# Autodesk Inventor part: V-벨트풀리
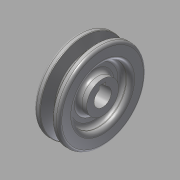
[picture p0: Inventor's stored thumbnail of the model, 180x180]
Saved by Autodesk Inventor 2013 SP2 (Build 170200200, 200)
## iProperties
Created: 2015-12
Part Number: V-벨트풀리
Material: 강철, 연강
Document SubType Name: Modeling
Designer: mduedu
Density: 7.86 g/cm^3
Author: mduedu
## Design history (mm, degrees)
sketch "스케치1"
  geometry: L1 (-9.5, 0)-(9.5, 0); L2 (-9.5, 0)-(-9.5, 32.7); L3 (-9.5, 32.7)-(-4.825, 32.7); L4 (-4.825, 32.7)-(-2.074, 23.7); L5 (-2.074, 23.7)-(0, 23.7); L6 (0, 0)-(0, 23.7); L7 (9.5, 0)-(9.5, 32.7); L8 (9.5, 32.7)-(4.825, 32.7); L9 (4.825, 32.7)-(2.074, 23.7); L10 (2.074, 23.7)-(0, 23.7); L11 (-4, 30)-(4, 30); 3 further points
  constraints: 22 end point, 3 coincident, 3 perpendicular, 3 symmetric about line, 2 parallel, 2 point on line, 1 horizontal, 1 midpoint, 1 vertical alignment
  dimensions: "d0" = 19 distance between parallel lines of L7 L2; "d2" = 6.3 distance between parallel lines of L10 L11; "d3" = 34 deg angle of L9 L4; "d4" = 2.7 distance between parallel lines of L11 L8; "d5" = 60 diameter of L11 L1; "d6" = 8 distance of L11.end L11.start
revolve "회전1" sketch "스케치1" stored, may be unused: angle "d7" = 90 deg
sketch "스케치2"
  geometry: C1 r 21 at (0, 0); C2 r 12 at (0, 0); 1 further point
  constraints: 2 centre point, 2 coincident
  dimensions: "d8" = 42 diameter of C1; "d10" = 24 diameter of C2
extrude "돌출1" cut sketch "스케치2" distance "d11" = 6.5; taper "d12" = 0 deg
fillet "모깎기1" dims "d13" = 1, "d14" = 0.5, "d15" = 2
fillet "모깎기2" dims "d16" = 3
fillet "모깎기3" dims "d17" = 3
hole "구멍1" diameter "d20" = 13; stored, may be unused: countersink angle "d24" = 90 deg, drill point angle "d26" = 118 deg; dims "d18" = 10, "d19" = 10, "d21" = 6, "d22" = 4, "d23" = 2, "d25" = 8
sketch "스케치3"
  geometry: L1 (-2.5, 0)-(2.5, 0); L2 (2.5, 0)-(2.5, 8.8); L3 (2.5, 8.8)-(-2.5, 8.8); L4 (-2.5, 8.8)-(-2.5, 0); 2 further points
  constraints: 8 end point, 2 parallel, 1 coincident, 1 horizontal, 1 midpoint, 1 perpendicular
  dimensions: "d27" = 8.8 distance of L1.end L2.end; "d29" = 5 distance of L2.end L3.end
extrude "돌출2" cut sketch "스케치3" stored distance "d30" = 6.5; taper "d31" = 0 deg
node "솔리드1"
mirror "대칭1"
